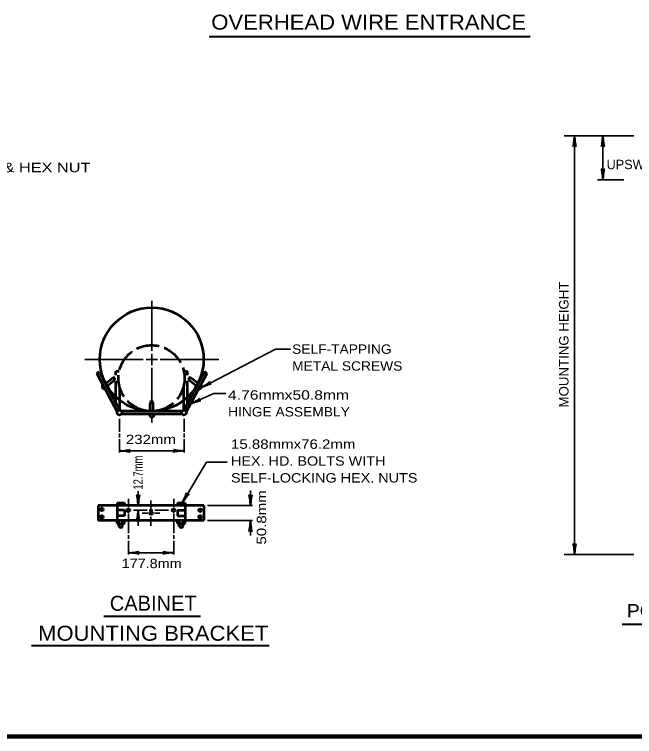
# Model space of a CAD drawing. Extents: x -23 to 690, y -228 to 443.
# Drawn here: x 190.5 to 356, y -0.6 to 192.2 of the extents above; entities that cross this region are included whole.
import ezdxf
from ezdxf.enums import TextEntityAlignment as Align

# ---------------------------------------------------------------- set-up
doc = ezdxf.new("R2010")
doc.units = 0
doc.linetypes.add('LONG_DASHED', pattern=[7.5, 6, -1.5])
doc.layers.add('1', color=7, linetype='Continuous', lineweight=35)

msp = doc.modelspace()

# ---------------------------------------------------------------- linework, layer by layer
at = {"layer": '1', "lineweight": 40}
for p, q in [((242.425, 186.371), (328.129, 186.371)), ((214.337, 31.579), (240.132, 31.579)), ((352.69, 29.414), (407.27, 29.414)), ((195.038, 23.685), (258.509, 23.685))]:
    msp.add_line(p, q, dxfattribs=at)
at = {"layer": '1'}
for p, q in [((355.77, 159.854), (337.171, 159.854)), ((339.971, 159.854), (339.971, 47.974)), ((347.53, 148.054), (347.53, 159.854)), ((353.171, 148.054), (346.13, 148.054)), ((227.134, 115.748), (227.134, 102.388)), ((240.289, 92.534), (260.144, 102.807)), ((260.144, 102.807), (264.151, 102.824)), ((227.134, 101.627), (227.134, 98.608)), ((209.234, 100.127), (224.874, 100.127)), ((225.614, 100.127), (228.654, 100.127)), ((229.394, 100.127), (245.014, 100.127)), ((227.134, 97.847), (227.134, 89.407)), ((218.511, 84.285), (218.511, 80.785)), ((227.134, 84.487), (227.134, 83.227)), ((235.796, 84.285), (235.796, 80.785)), ((218.511, 80.285), (218.511, 79.285)), ((235.796, 80.285), (235.796, 79.285)), ((218.511, 78.785), (218.511, 75.285)), ((235.796, 78.785), (235.796, 75.285)), ((218.511, 75.692), (235.796, 75.692)), ((235.269, 61.828), (241.758, 72.646)), ((241.758, 72.646), (247.232, 72.707)), ((223.503, 61.067), (223.503, 64.886)), ((253.482, 61.067), (253.482, 65.067)), ((220.894, 62.907), (220.894, 60.688)), ((226.934, 62.468), (226.934, 60.067)), ((232.994, 62.907), (232.994, 60.688)), ((222.274, 59.807), (225.934, 59.807)), ((223.503, 55.707), (223.503, 59.807)), ((226.434, 59.807), (227.454, 59.807)), ((227.954, 59.807), (231.594, 59.807)), ((242.054, 61.067), (254.054, 61.067)), ((220.894, 58.927), (220.894, 53.669)), ((224.554, 59.067), (226.074, 59.067)), ((226.934, 58.047), (226.934, 55.707)), ((227.834, 59.067), (229.294, 59.067)), ((232.994, 58.927), (232.994, 53.669)), ((242.054, 57.047), (254.054, 57.047)), ((253.482, 53.047), (253.482, 57.047)), ((220.894, 53.169), (220.894, 52.169)), ((232.994, 53.169), (232.994, 52.169)), ((220.894, 51.669), (220.894, 47.968)), ((232.994, 51.669), (232.994, 47.968)), ((220.894, 48.468), (232.994, 48.468)), ((355.77, 47.974), (337.171, 47.974))]:
    msp.add_line(p, q, dxfattribs=at)
at = {"layer": '1', "lineweight": 53}
for p, q in [((212.474, 96.328), (213.114, 96.847)), ((213.114, 96.847), (218.614, 86.507)), ((241.174, 96.847), (235.674, 86.528)), ((241.814, 96.328), (241.174, 96.847)), ((212.474, 96.328), (217.934, 86.067)), ((241.814, 96.328), (236.354, 86.067)), ((235.254, 85.507), (219.014, 85.507)), ((235.234, 86.248), (219.054, 86.248)), ((217.874, 61.828), (219.894, 61.828)), ((218.374, 61.828), (218.374, 61.067)), ((219.374, 61.828), (219.374, 61.067)), ((219.894, 61.828), (219.894, 61.067)), ((233.994, 61.828), (233.994, 61.067)), ((233.994, 61.828), (236.014, 61.828)), ((234.494, 61.828), (234.494, 61.067)), ((235.514, 61.828), (235.514, 61.067)), ((241.054, 61.067), (212.834, 61.067)), ((212.834, 61.067), (212.834, 57.047)), ((219.894, 59.807), (217.874, 59.807)), ((219.894, 59.807), (219.894, 58.307)), ((233.994, 59.807), (233.994, 58.307)), ((233.994, 59.807), (236.014, 59.807)), ((241.054, 61.067), (241.054, 57.047)), ((219.894, 58.307), (217.874, 58.307)), ((233.994, 58.307), (236.014, 58.307)), ((241.054, 57.047), (212.834, 57.047)), ((217.874, 56.247), (217.874, 57.008)), ((217.874, 56.247), (219.894, 56.247)), ((218.374, 55.508), (218.374, 57.008)), ((219.374, 55.508), (219.374, 57.008)), ((219.894, 56.247), (219.894, 57.008)), ((233.994, 56.247), (233.994, 57.008)), ((233.994, 56.247), (236.014, 56.247)), ((234.494, 55.508), (234.494, 57.008)), ((235.514, 55.508), (235.514, 57.008)), ((236.014, 56.247), (236.014, 57.008)), ((218.374, 55.508), (219.374, 55.508)), ((234.494, 55.508), (235.514, 55.508))]:
    msp.add_line(p, q, dxfattribs=at)
at = {"layer": '1', "linetype": 'LONG_DASHED', "lineweight": 53}
for p, q in [((217.594, 88.407), (217.594, 96.987)), ((217.594, 96.987), (218.454, 96.987)), ((235.674, 96.987), (236.694, 96.987)), ((236.694, 88.407), (236.694, 96.987)), ((214.794, 93.667), (216.394, 94.907)), ((239.494, 93.667), (237.894, 94.907)), ((215.154, 92.987), (216.854, 94.328)), ((218.614, 86.507), (218.614, 92.587)), ((235.674, 86.528), (235.674, 93.168)), ((239.114, 92.987), (237.434, 94.328)), ((226.754, 86.248), (226.754, 88.227)), ((227.514, 86.248), (227.514, 88.227))]:
    msp.add_line(p, q, dxfattribs=at)
at = {"layer": '1', "lineweight": 158}
msp.add_line((684.026, -0.611), (24.36, -0.611), dxfattribs=at)
at = {"layer": '1'}
msp.add_lwpolyline([(237.498, 88.217), (243.677, 90.992), (246.865, 90.992)], dxfattribs=at)
at = {"layer": '1', "lineweight": 53}
for points in [[(217.874, 61.828), (217.874, 61.067), (217.874, 57.047)], [(236.014, 61.828), (236.014, 61.067), (236.014, 57.047)]]:
    msp.add_lwpolyline(points, dxfattribs=at)
for centre, radius in [((227.133, 100.114), 13.86), ((218.531, 85.891), 0.63), ((235.74, 85.891), 0.63), ((213.837, 60.067), 0.378), ((220.888, 59.806), 0.378), ((232.984, 59.806), 0.378), ((240.055, 59.806), 0.378), ((213.837, 58.049), 0.378), ((226.948, 59.048), 0.378), ((240.029, 58.037), 0.378)]:
    msp.add_circle(centre, radius, dxfattribs=at)
at = {"layer": '1', "linetype": 'LONG_DASHED', "lineweight": 53}
msp.add_circle((227.068, 95.077), 8.82, dxfattribs=at)
at = {"layer": '1', "lineweight": 53}
for centre, radius, start, end in [((214.544, 92.942), 0.681, 138.1398, 277.864), ((239.754, 92.956), 0.681, 262.136, 41.8602), ((227.183, 85.365), 0.63, 167.65166, 11.75169), ((218.877, 55.792), 0.582, 209.9862, 330.0138), ((235.005, 55.756), 0.565, 206.79037, 333.20963)]:
    msp.add_arc(centre, radius, start, end, dxfattribs=at)
at = {"layer": '1', "lineweight": 40}
for centre, major_axis, ratio, start_param, end_param in [((339.766, 158.731), (0.177, 1.77), 0.07063, 3.1407148, 5.41811), ((340.258, 158.761), (-0.157, 1.8), 0.122415, 0.8963533, 3.1415927), ((347.327, 158.731), (0.177, 1.77), 0.07063, 3.1407148, 5.41811), ((347.818, 158.761), (-0.157, 1.8), 0.122415, 0.8963533, 3.1415927), ((347.261, 149.148), (0.157, -1.8), 0.122415, 0.8963533, 3.1415927), ((347.753, 149.178), (-0.177, -1.77), 0.07063, 3.1407148, 5.41811), ((241.131, 93.281), (-1.514, -0.959), 0.122415, 0.8963533, 3.1415927), ((241.131, 93.281), (-1.514, -0.959), 0.122415, 0.8963533, 3.1415927), ((241.381, 92.861), (1.641, 0.651), 0.07063, 6.2823074, 8.5597026), ((241.381, 92.861), (1.641, 0.651), 0.07063, 6.2823074, 8.5597026), ((238.38, 88.916), (-1.565, -0.874), 0.122415, 0.8963533, 3.1415927), ((238.607, 88.483), (-1.674, -0.559), 0.07063, 3.1407148, 5.41811), ((219.631, 75.481), (-1.756, 0.176), 0.07063, 3.1407148, 5.41811), ((219.631, 75.481), (-1.756, 0.176), 0.07063, 3.1407148, 5.41811), ((219.602, 75.969), (-1.786, -0.156), 0.122415, 0.8963533, 3.1415927), ((219.602, 75.969), (-1.786, -0.156), 0.122415, 0.8963533, 3.1415927), ((234.705, 75.416), (1.786, 0.156), 0.122415, 0.8963533, 3.1415927), ((234.705, 75.416), (1.786, 0.156), 0.122415, 0.8963533, 3.1415927), ((234.675, 75.904), (1.756, -0.176), 0.07063, 3.1407148, 5.41811), ((234.675, 75.904), (1.756, -0.176), 0.07063, 3.1407148, 5.41811), ((223.227, 62.159), (0.156, -1.786), 0.122415, 0.8963533, 3.1415927), ((223.227, 62.159), (0.156, -1.786), 0.122415, 0.8963533, 3.1415927), ((223.715, 62.188), (-0.176, -1.756), 0.07063, 3.1407148, 5.41811), ((223.715, 62.188), (-0.176, -1.756), 0.07063, 3.1407148, 5.41811), ((235.593, 62.905), (-0.785, -1.612), 0.122415, 0.8963533, 3.1415927), ((236.027, 62.68), (1.054, 1.416), 0.07063, 6.2823074, 8.5597026), ((253.205, 62.159), (0.156, -1.786), 0.122415, 0.8963533, 3.1415927), ((253.205, 62.159), (0.156, -1.786), 0.122415, 0.8963533, 3.1415927), ((253.693, 62.188), (-0.176, -1.756), 0.07063, 3.1407148, 5.41811), ((253.693, 62.188), (-0.176, -1.756), 0.07063, 3.1407148, 5.41811), ((223.292, 58.687), (0.176, 1.756), 0.07063, 3.1407148, 5.41811), ((223.292, 58.687), (0.176, 1.756), 0.07063, 3.1407148, 5.41811), ((223.779, 58.716), (-0.156, 1.786), 0.122415, 0.8963533, 3.1415927), ((223.779, 58.716), (-0.156, 1.786), 0.122415, 0.8963533, 3.1415927), ((253.27, 55.927), (0.176, 1.756), 0.07063, 3.1407148, 5.41811), ((253.27, 55.927), (0.176, 1.756), 0.07063, 3.1407148, 5.41811), ((253.758, 55.956), (-0.156, 1.786), 0.122415, 0.8963533, 3.1415927), ((253.758, 55.956), (-0.156, 1.786), 0.122415, 0.8963533, 3.1415927), ((339.701, 49.073), (0.157, -1.8), 0.122415, 0.8963533, 3.1415927), ((340.193, 49.102), (-0.177, -1.77), 0.07063, 3.1407148, 5.41811), ((221.985, 48.744), (-1.786, -0.156), 0.122415, 0.8963533, 3.1415927), ((221.985, 48.744), (-1.786, -0.156), 0.122415, 0.8963533, 3.1415927), ((222.015, 48.257), (-1.756, 0.176), 0.07063, 3.1407148, 5.41811), ((222.015, 48.257), (-1.756, 0.176), 0.07063, 3.1407148, 5.41811), ((231.903, 48.192), (1.786, 0.156), 0.122415, 0.8963533, 3.1415927), ((231.873, 48.68), (1.756, -0.176), 0.07063, 3.1407148, 5.41811)]:
    msp.add_ellipse(centre, major_axis=major_axis, ratio=ratio, start_param=start_param, end_param=end_param, dxfattribs=at)
at = {"layer": '1', "linetype": 'LONG_DASHED', "lineweight": 53}
for centre, major_axis, start_param, end_param in [((216.623, 94.618), (0.664, 0.518), 4.712389, 7.8539816), ((237.663, 94.618), (0.664, -0.518), 1.5707963, 4.712389), ((227.13, 88.236), (0.003, -0.842), 1.5707963, 4.712389)]:
    msp.add_ellipse(centre, major_axis=major_axis, ratio=0.448678, start_param=start_param, end_param=end_param, dxfattribs=at)

# ---------------------------------------------------------------- texts
at = {"layer": '1'}
for s, height, width, p in [('OVERHEAD WIRE ENTRANCE', 4, 1.1, (243.028, 188.18)), ('15.88mm BOLT & HEX NUT', 2.5, 1.3, (155.71, 150.116)), ('SELF-TAPPING', 2.5, 1.1, (264.593, 101.604)), ('METAL SCREWS', 2.5, 1.1, (264.593, 97.104)), ('4.76mmx50.8mm', 2.5, 1.25, (247.504, 89.371)), ('HINGE ASSEMBLY', 2.5, 1.1, (247.504, 84.871)), ('232mm', 2.5, 1.2, (220.226, 77.508)), ('15.88mmx76.2mm', 2.5, 1.2, (248.28, 76.237)), ('HEX. HD. BOLTS WITH', 2.5, 1.15, (248.28, 71.737)), ('SELF-LOCKING HEX. NUTS', 2.5, 1.15, (248.28, 67.237)), ('177.8mm', 2.5, 1.15, (219.097, 44.363)), ('POLE COMPONENTS', 3.528, 1.1, (353.911, 31.234))]:
    msp.add_text(s, height=height, dxfattribs=dict(at, width=width)).set_placement(p)
msp.add_text('UPSWEEP', height=2.52, dxfattribs=at).set_placement((348.55, 150.914))
for s, height, width, p in [('MOUNTING HEIGHT', 2.52, 1.05, (338.37, 87.274)), ('12.7mm', 2.5, 0.75, (224.714, 65.332)), ('50.8mm', 2.5, 1.2, (257.672, 50.661))]:
    msp.add_text(s, height=height, rotation=90, dxfattribs=dict(at, width=width)).set_placement(p)
msp.add_text('CABINET', height=4, dxfattribs=at).set_placement((227.528, 32.987), align=Align.CENTER)
at = {"layer": '1', "width": 1.1}
msp.add_text('MOUNTING BRACKET', height=4, dxfattribs=at).set_placement((227.528, 24.987), align=Align.CENTER)

doc.saveas('drawing.dxf')
